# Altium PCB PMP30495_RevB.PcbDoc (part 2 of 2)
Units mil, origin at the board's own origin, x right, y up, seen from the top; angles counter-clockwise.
Board outline 6212.5 x 2387.5 mil, 2 copper layers (Top Layer, Bottom Layer), stack 62 mil thick; 95 components, 48 nets, 204 pads, 17 vias.
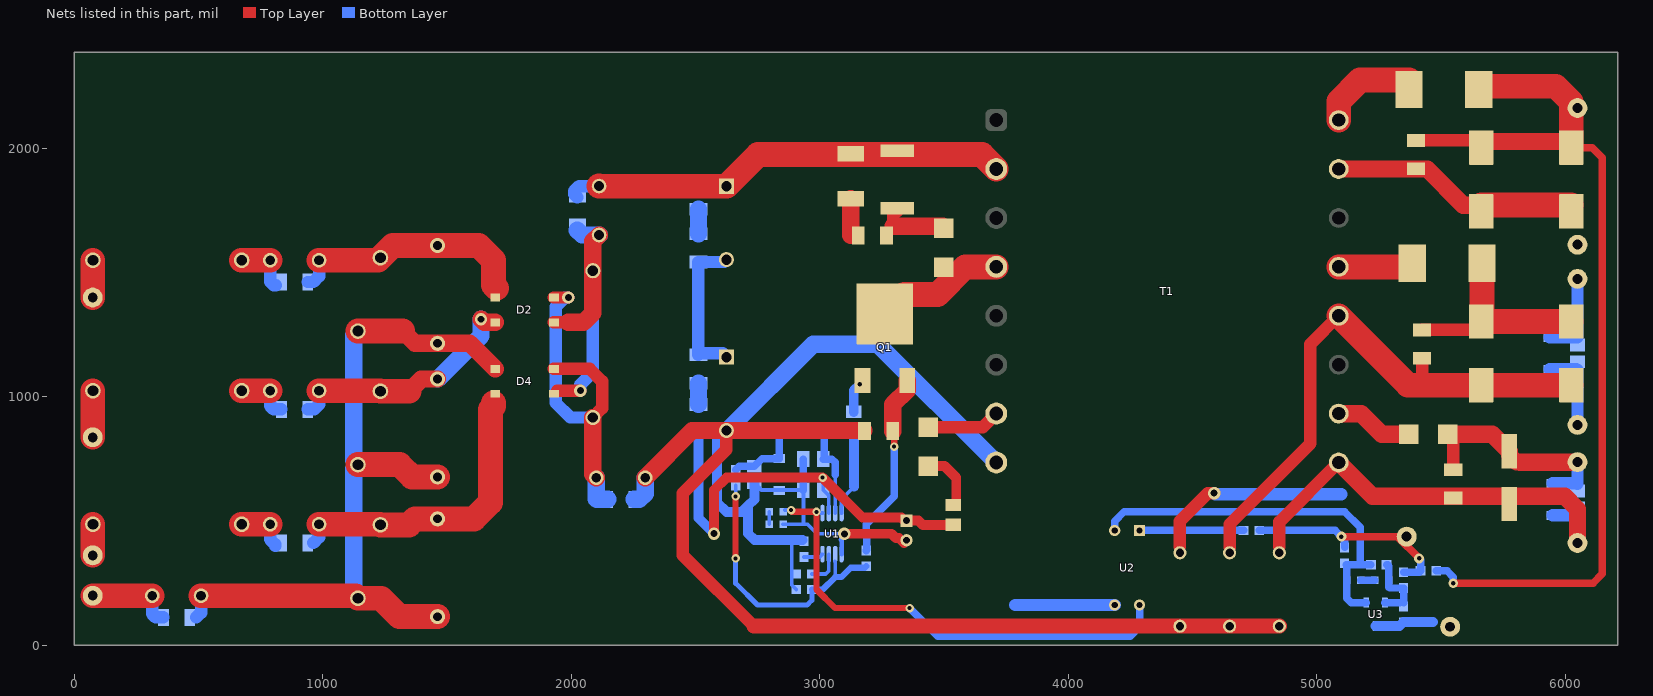
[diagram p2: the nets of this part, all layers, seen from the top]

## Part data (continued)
U3: "2.5V Low Iq Adjustable Precision Shunt Regulator, DBZ0003A (SOT-23-3)", Alternate Manufacturer="Texas Instruments"

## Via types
v1: diameter 34, hole 16, Top Layer to Bottom Layer, 7 vias
v2: diameter 50, hole 28, Top Layer to Bottom Layer, 6 vias
v3: diameter 40, hole 18, Top Layer to Bottom Layer, 4 vias

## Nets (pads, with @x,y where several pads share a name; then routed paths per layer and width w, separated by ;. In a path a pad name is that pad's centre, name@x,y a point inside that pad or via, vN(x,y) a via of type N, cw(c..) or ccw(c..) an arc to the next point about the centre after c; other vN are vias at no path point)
12Vout1: C3.1 C4.1 C5.1 D1.1 R16.2 TP2.1 | length 3730.7
  Top Layer w30: v3(5550,250) 6112.5,250 6150,287.5 6150,1962.5 6109.55,2002.95 C3.1@6025,2002.95
  Top Layer w50: C5.1@5400,2032.09 5633.37,2032.09 C4.1@5662.5,2002.95
  Top Layer w70: C4.1@5662.5,2027.95 C3.1@6025,2027.95
  Top Layer w100: D1.1@5652.99,2250 5962.5,2250 6025,2187.5 C3.1@6025,2027.95
  Bottom Layer w30: R16.2@5481.5,300 5525,300 5550,275 v3(5550,250)
GND1: C3.2 C4.2 C5.2 C16.1 R27.1 T1.15 TP3.1 TP12.1 U3.3 | length 2034.4
  Top Layer w50: C16.1@4450,397.64 4450,500 4562.5,612.5 v2(4587.5,612.5)
  Top Layer w70: T1.15@5088.98,1917.13 5445.37,1917.13 5590.45,1772.05 C4.2@5662.5,1772.05
  Top Layer w100: C4.2@5662.5,1772.05 C3.2@6025,1772.05
  Bottom Layer w40: U3.3@5237.5,77.76 5334.25,77.76 R27.1@5350,93.5 5468.5,93.5
  Bottom Layer w50: v2(4587.5,612.5) 4591.93,608.07 5100,608.07
GND2: C10.2 C11.2 C12.2 C18.1 D6.2 R10.1 T1.12 TP7.1 | length 2607.5
  Top Layer w50: C18.1@4650,394.29 4650,487.5 4975,812.5 4975,1212.6 T1.12@5088.98,1326.57 ; 5425,1047.05 C12.2@5425,1155.41
  Top Layer w100: T1.12@5088.98,1326.57 5368.5,1047.05 5425,1047.05 C10.2@5662.5,1047.05 C11.2@6025,1047.05
  Bottom Layer w50: D6.2@5937.5,1110.53 6044.59,1110.53 cw(c6044.59,1105.12) 6050,1105.12 TP7.1@6050,887.5
GND3: C14.2 C15.2 C19.1 D9.2 R14.1 T1.9 TP10.1 | length 1825.5
  Top Layer w50: C19.1@4850,397.64 4850,497.05 T1.9@5088.98,736.02
  Top Layer w70: T1.9@5088.98,736.02 5225,600 5998.13,600 6050,548.13 TP10.1@6050,412.5
  Bottom Layer w50: D9.2@5950,523.03 6048.03,523.03 ccw(c6048.03,525) 6050,525 TP10.1@6050,412.5
NetC1_1: C1.1 D2.3 L1.2 R1.2 RV1.2 | length 951.5
  Top Layer w100: L1.2@985.93,1550 1222.64,1550 RV1.2@1232.78,1560.14 1281.99,1609.35 C1.1@1462.5,1609.35 1628.15,1609.35 1687.5,1550 1687.5,1450 1700,1437.5
  Bottom Layer w50: R1.2@940.65,1462.5 962.5,1462.5 985.93,1485.93 985.93,1514.07
NetC1_2: C1.2 C7.2 C13.2 D4.3 L6.2 R15.2 RV1.1 RV2.1 RV3.1 | length 3127.3
  Top Layer w70: 1322.64,1264.86 1371.85,1215.65 C1.2@1462.5,1215.65 1591.24,1215.65 D4.3@1694.39,1112.5
  Top Layer w100: L6.2@510.93,200 RV3.1@1132.09,200 ; RV3.1@1142.22,189.86 1235.14,189.86 1309.35,115.65 C13.2@1462.5,115.65 ; RV2.1@1142.22,727.36 1310.14,727.36 1359.35,678.15 C7.2@1462.5,678.15 ; RV1.1@1142.22,1264.86 1322.64,1264.86
  Bottom Layer w50: 491.24,112.5 510.93,132.18 L6.2@510.93,200
  Bottom Layer w70: RV3.1@1142.22,189.86 1125,207.09 1125,710.14 RV2.1@1142.22,727.36 1125,744.59 1125,1247.64 RV1.1@1142.22,1264.86
NetC2_1: C2.1 L2.2 R2.2 R3.2 R4.2 R6.2 T1.2 | length 1936.1
  Top Layer w100: L2.2@2112.5,1848.43 2113.29,1847.64 C2.1@2625,1847.64 2752.36,1975 3653.15,1975 T1.2@3711.02,1917.13
  Bottom Layer w50: R2.2@2025,1803.15 2012.5,1815.65 2012.5,1828.74 2032.18,1848.43 L2.2@2112.5,1848.43 ; R3.2@2512.5,1869.59 2603.05,1869.59 C2.1@2625,1847.64
NetC2_2: C2.2 C9.1 R5.1 R9.2 | length 610.6
  Bottom Layer w50: C9.1@2625,1160.14 2610.14,1175 2517.91,1175 R9.2@2512.5,1169.59 R5.1@2512.5,1542.91 2615.55,1542.91 C2.2@2625,1552.36
NetC6_1: C6.1 D2.1 D4.1 L2.1 R2.1 | length 1190.4
  Top Layer w50: D2.1@1930.61,1300 1989.07,1300 ; D4.1@1943.11,1025 v2(2037.5,1025)
  Top Layer w70: 1989.07,1300 2050,1300 2087.5,1337.5 C6.1@2087.5,1507.78 2087.5,1626.57 L2.1@2112.5,1651.57
  Bottom Layer w50: v2(2037.5,1025) 2037.5,1050 2087.5,1100 C6.1@2087.5,1507.78
  Bottom Layer w70: 2025,1671.26 2044.68,1651.57 L2.1@2112.5,1651.57
NetC6_2: C6.2 D2.4 D4.4 L4.1 R8.1 | length 1441.9
  Top Layer w50: D4.4@1930.61,1112.5 2075,1112.5 2125,1062.5 2125,954.72 C6.2@2087.5,917.22 ; D2.4@1930.61,1400 v2(1989.07,1400)
  Top Layer w70: C6.2@2087.5,917.22 2087.5,689.07 L4.1@2101.57,675
  Bottom Layer w50: v2(1989.07,1400) 1975,1400 1937.5,1362.5 1937.5,976.57 1996.85,917.22 C6.2@2087.5,917.22
  Bottom Layer w70: L4.1@2101.57,675 2101.57,589.07 2103.15,587.5 R8.1@2146.85,587.5
NetC7_1: C7.1 D2.2 L3.2 R7.2 RV2.2 | length 981.9
  Top Layer w70: 1347.64,1022.64 1396.85,1071.85 C7.1@1462.5,1071.85 ; v2(1637.5,1312.5) 1650,1300 D2.2@1694.39,1300
  Top Layer w100: L3.2@985.93,1025 1230.41,1025 RV2.2@1232.78,1022.64 1347.64,1022.64
  Bottom Layer w50: R7.2@940.65,950 966.24,950 985.93,969.68 L3.2@985.93,1025
  Bottom Layer w70: C7.1@1462.5,1071.85 1637.5,1246.85 v2(1637.5,1312.5)
NetC8_1: C8.1 R4.1 | length 146.9
  Top Layer w70: 3125,1650 R4.1@3125,1796.95
NetC8_2: C8.2 D5.1 R6.1 | length 276.9
  Top Layer w50: 3296.26,1687.5 3296.26,1730.12 cw(c3312.5,1730.12) R6.1@3312.5,1746.36
  Top Layer w70: 3296.26,1687.5 3491.24,1687.5 cw(c3491.24,1678.74) D5.1@3500,1678.74
NetC10_1: C10.1 C11.1 C12.1 D3.1 D6.1 R10.2 TP5.1 | length 1196.3
  Top Layer w50: C12.1@5425,1269.59 5629.13,1269.59 C10.1@5662.5,1302.95
  Top Layer w100: D3.1@5665.49,1537.5 5665.49,1305.95 C10.1@5662.5,1302.95 C11.1@6025,1302.95
  Bottom Layer w50: D6.1@5937.5,1239.47 6046.87,1239.47 ccw(c6046.87,1242.6) 6050,1242.6 TP5.1@6050,1475
NetC13_1: C13.1 D4.2 L5.2 R12.2 RV3.2 | length 1213.8
  Top Layer w100: L5.2@985.93,487.5 RV3.2@1230.41,487.5 ; RV3.2@1232.78,485.14 1347.64,485.14 1371.85,509.35 C13.1@1462.5,509.35 1609.35,509.35 1675,575 1675,950 1687.5,962.5 1687.5,975
  Bottom Layer w50: 962.5,412.5 985.93,435.93 L5.2@985.93,487.5
NetC14_1: C14.1 C15.1 D7.1 D9.1 R14.2 TP8.1 | length 915.1
  Top Layer w50: D7.1@5528.74,850 5550,828.74 C15.1@5550,707.09
  Top Layer w70: D7.1@5528.74,850 5706.3,850 C14.1@5775,781.3 ccw(c5818.8,781.3) 5818.8,737.5 TP8.1@6050,737.5
  Bottom Layer w50: D9.1@5950,651.97 6048.03,651.97 cw(c6048.03,650) 6050,650 TP8.1@6050,737.5
NetC17_1: C17.1 C20.1 R11.1 R13.1 U1.2 | length 1820.8
  Top Layer w40: v2(2575,450) 2575,625 2625,675 v1(3012.5,675) 3173.29,514.21 3329.58,514.21 3341.92,501.87 C17.1@3350,501.87 3398.13,501.87 3415,485 R13.1@3537.5,485
  Bottom Layer w15: v1(3012.5,675) 3015,672.5 C20.1@3015,625 3037.2,602.8 U1.2@3037.2,532.68
  Bottom Layer w40: R11.1@2512.5,855.41 2512.5,512.5 v2(2575,450)
NetC21_1: C21.1 R19.1 R25.1 R27.2 U3.2 | length 274.7
  Bottom Layer w30: U3.2@5274.9,172.24 R27.2@5334.25,172.24 ; C21.1@5281.5,325 cw(c5281.5,316) 5290.5,316 R25.1@5290.5,262.5 5290.5,234.5 5294,231 R19.1@5350,231 R27.2@5350,172.24
NetC21_2: C21.2 C25.1 R18.1 U2.2 U3.1 | length 1533.1
  Bottom Layer w30: U2.2@4187.5,462.5 4187.5,500 4225,537.5 5112.5,537.5 5175,475 5175,325 ; R18.1@5118.5,325 5175,325 ; R18.1@5122,321.5 C25.1@5122,262.5 5122,190.5 5140.26,172.24 U3.1@5200.1,172.24 ; C21.2@5218.5,325 5175,325
NetC22_1: C22.1 U1.8 | length 78.8
  Bottom Layer w15: C22.1@2937.5,356 3000.3,356 U1.8@3011.61,367.32
NetC23_1: C23.1 R26.2 U1.3 | length 371.8
  Bottom Layer w15: U1.3@3062.8,532.68 3062.8,687.2
  Bottom Layer w30: R26.2@3019,862.5 3019,754 C23.1@3015,750 3050,750 3062.8,737.2 3062.8,687.2
NetC24_1: C24.1 R20.1 R28.2 U1.6 | length 1127.6
  Top Layer w25: v1(2661.82,599.5) 2661.82,350.68 v1(2662.5,350)
  Bottom Layer w15: v1(2661.82,599.5) 2661.82,590.68 2662.5,590 R28.2@2662.5,643.5 ; U1.6@3061.44,337.7 3062.5,336.64 3062.5,275
  Bottom Layer w20: v1(2662.5,350) 2662.5,250 2750,162.5 2950,162.5 2969,181.5 C24.1@2969,225
  Bottom Layer w25: C24.1@2969,225 3012.5,225 3062.5,275 3087.5,275 3125,312.5 3181.5,312.5 R20.1@3187.5,318.5
NetC25_2: C25.2 R25.2 | length 56.5
  Bottom Layer w30: C25.2@5178,262.5 R25.2@5234.5,262.5
NetC26_1: C26.1 R22.1 | length 50
  Bottom Layer w15: C26.1@2797,487.5 R22.1@2797,537.5
NetC27_1: C27.1 D10.1 R26.1 R28.1 | length 408.2
  Bottom Layer w30: R28.1@2662.5,706.5 2676.97,720.96 C27.1@2737.5,720.96 2768.5,751.97 D10.1@2837.5,751.97 2837.5,837.5 2862.5,862.5 R26.1@2956,862.5
NetD1_2: D1.2 T1.16 | length 393.7
  Top Layer w100: T1.16@5088.98,2113.98 5088.98,2188.98 5175,2275 D1.2@5372.01,2275
NetD3_2: D3.2 T1.13 | length 281.5
  Top Layer w100: T1.13@5088.98,1523.43 D3.2@5370.43,1523.43
NetD5_2: D5.2 Q1.4 T1.4 | length 415.8
  Top Layer w100: Q1.4@3341.14,1412.5 3475,1412.5 3585.93,1523.43 T1.4@3711.02,1523.43
NetD7_2: D7.2 T1.10 | length 316.6
  Top Layer w70: T1.10@5088.98,932.87 5179.63,932.87 5262.5,850 D7.2@5371.26,850
NetD8_1: D8.1 R13.2 | length 246.8
  Top Layer w40: D8.1@3437.5,721.26 3503.74,721.26 3550,675 3550,577.5 R13.2@3537.5,565
NetD8_2: D8.2 T1.7 | length 295.9
  Top Layer w50: D8.2@3437.5,878.74 3656.89,878.74 T1.7@3711.02,932.87
NetL1_1: L1.1 R1.1 RF1.1 | length 230
  Top Layer w100: RF1.1@674.21,1550 L1.1@789.07,1550
  Bottom Layer w50: L1.1@789.07,1550 789.07,1464.07 803.15,1450 812.5,1450
NetL3_1: L3.1 R7.1 RF2.1 | length 226.9
  Top Layer w100: RF2.1@674.21,1025 L3.1@789.07,1025
  Bottom Layer w50: L3.1@789.07,1025 789.07,964.07 803.15,950 R7.1@834.35,950
NetL5_1: L5.1 R12.1 RF3.1 | length 210.5
  Top Layer w100: RF3.1@674.21,487.5 L5.1@789.07,487.5
  Bottom Layer w50: L5.1@789.07,487.5 789.07,426.57 808.76,406.89 808.76,400
NetL6_1: L6.1 R15.1 TP9.1 | length 363.6
  Top Layer w100: TP9.1@75,200 L6.1@314.07,200
  Bottom Layer w50: L6.1@314.07,200 314.07,126.57 328.15,112.5 R15.1@359.35,112.5
NetQ1_1: Q1.1 R17.2 | length 143.2
  Top Layer w40: v3(3162.5,1050) Q1.1@3178.64,1066.14
  Bottom Layer w40: R17.2@3137.5,940 3137.5,1025 v3(3162.5,1050)
NetQ1_3: Q1.3 R20.2 R24.2 | length 759.4
  Top Layer w25: R24.2@3294.59,862.5 3300,857.09 v1(3300,800)
  Top Layer w70: R24.2@3294.59,862.5 3294.59,969.59 3352.26,1027.26 Q1.3@3352.26,1066.14
  Bottom Layer w30: R20.2@3187.5,381.5 3187.5,383.08 3190,385.58 3190,439.42 3187.5,441.92 3187.5,487.5 3300,600 v1(3300,800)
NetR3_1: R3.1 R5.2 | length 98.3
  Bottom Layer w70: R5.2@2512.5,1657.09 R3.1@2512.5,1755.41
NetR9_1: R9.1 R11.2 | length 85.8
  Bottom Layer w70: R11.2@2512.5,969.59 R9.1@2512.5,1055.41
NetR16_1: R16.1 R18.2 R19.2 R21.2 TP11.1 | length 853.8
  Top Layer w30: v3(5100,437.5) 5325,437.5 v3(5412.5,350)
  Bottom Layer w30: R21.2@4769,462.5 5075,462.5 v3(5100,437.5) 5112.5,425 R18.2@5112.5,394 ; R19.2@5350,294 R16.1@5412.5,294 ; v3(5412.5,350) 5418.5,344 R16.1@5418.5,300
NetR17_1: R17.1 U1.4 | length 348.4
  Bottom Layer w15: U1.4@3088.39,532.68 3088.39,588.39 3138.39,638.39
  Bottom Layer w40: R17.1@3137.5,860 3138.39,859.11 3138.39,638.39
NetR21_1: R21.1 U2.1 | length 418.5
  Bottom Layer w30: U2.1@4287.5,462.5 R21.1@4706,462.5
NetR22_2: R22.2 U1.1 U2.4 | length 1971.5
  Top Layer w25: v1(2885.5,544.5) ccw(c2892.5,544.5) 2892.5,537.5 v1(2987.5,537.5) 2987.5,225 3062.5,150 v1(3362.5,150)
  Bottom Layer w15: R22.2@2860,544.5 v1(2885.5,544.5) ; v1(2987.5,537.5) 2977.17,537.5 2981.99,532.68 U1.1@3011.61,532.68
  Bottom Layer w30: v1(3362.5,150) 3475,37.5 4250,37.5 4287.5,75 U2.4@4287.5,162.5
NetR23_2: R23.2 U1.7 | length 140.9
  Bottom Layer w15: R23.2@2969,287.5 3025,287.5 3037.2,299.7 U1.7@3037.2,367.32
NetRF1_2: RF1.2 TP1.1 | length 149.2
  Top Layer w100: TP1.1@75,1400 RF1.2@75,1549.21
NetRF2_2: RF2.2 TP4.1 | length 186.7
  Top Layer w100: TP4.1@75,837.5 RF2.2@75,1024.21
NetRF3_2: RF3.2 TP6.1 | length 124.2
  Top Layer w100: TP6.1@75,362.5 RF3.2@75,486.71
PGND: C9.2 C16.2 C17.2 C18.2 C19.2 C20.2 C22.2 C23.2 C24.2 C26.2 C27.2 D10.2 L4.2 R8.2 R23.1 R24.1 T1.8 U1.5 U2.3 | length 8194.3
  Top Layer w40: v2(3100,449.21) 3289.81,449.21 3306.75,432.26 3319.61,432.26 C17.2@3339.37,412.5
  Top Layer w50: C9.2@2625,864.86 2625,787.5 2450,612.5 2450,362.5 2735.14,77.36
  Top Layer w60: 2735.14,77.36 4537.5,77.36 C19.2@4850,77.36
  Top Layer w70: L4.2@2298.43,675 2488.29,864.86 C9.2@2625,864.86 R24.1@3178.05,864.86
  Bottom Layer w15: C27.2@2737.5,654.04 2766.54,625 C20.2@2935,625 2935,487.5 ; C26.2@2853,487.5 2935,487.5 ; C24.2@2906,225 2887.5,243.5 2887.5,412.5 2894,419 C22.2@2937.5,419 ; v2(3100,449.21) 2989.76,449.21 2951.48,487.5 2935,487.5
  Bottom Layer w18: 3084.43,425 3088.39,421.04 U1.5@3088.39,367.32
  Bottom Layer w30: C20.2@2935,625 C23.2@2935,750
  Bottom Layer w40: C9.2@2625,864.86 2587.5,827.36 2587.5,575 2625,537.5 2687.5,537.5 2712.5,562.5 ; C27.2@2737.5,654.04 2737.5,587.5 2712.5,562.5 ; C22.2@2931.5,425 2737.5,425 2712.5,450 2712.5,562.5
  Bottom Layer w50: 3787.5,162.5 U2.3@4187.5,162.5
  Bottom Layer w70: R8.2@2253.15,587.5 2275,587.5 2298.43,610.93 L4.2@2298.43,675 ; C9.2@2625,864.86 2627.36,864.86 2975,1212.5 3234.55,1212.5 T1.8@3711.02,736.02
pads on no net: T1.1 T1.3 T1.5 T1.6 T1.11 T1.14

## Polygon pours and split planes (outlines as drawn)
NetD5_2 on Top Layer "Top Layer-No Net" (solid, pour order 4): 3362.5,1487.5 ccw(c3362.5,1537.5) 3412.5,1537.5 cw(c3450,1537.5) 3450,1575 3712.5,1575 cw(c3712.5,1525) 3762.5,1525 3762.5,1512.5 cw(c3725,1512.5) 3725,1475 3612.5,1475 ccw(c3612.5,1462.5) 3600,1462.5 3600,1450 cw(c3512.5,1450) 3512.5,1362.5 3412.5,1362.5 ccw(c3412.5,1337.5) 3387.5,1337.5 3387.5,1225 cw(c3362.5,1225) 3362.5,1200 3150,1200 cw(c3150,1237.5) 3112.5,1237.5 3112.5,1437.5 cw(c3162.5,1437.5) 3162.5,1487.5
NetC8_2 on Top Layer "Top Layer-No Net 1" (solid, pour order 6): 3260.73,1800 ccw(c3260.73,1775) 3235.73,1775 3235.73,1630.51 ccw(c3262.5,1630.51) 3262.5,1603.74 3366.24,1603.74 ccw(c3366.24,1625) 3387.5,1625 cw(c3400,1625) 3400,1637.5 3543.9,1637.5 ccw(c3543.9,1662.5) 3568.9,1662.5 3568.9,1768.6 ccw(c3537.5,1768.6) 3537.5,1800
NetC8_1 on Top Layer "Top Layer-No Net 2" (solid, pour order 8): 3137.5,1602.36 3164.86,1602.36 ccw(c3164.86,1625) 3187.5,1625 3187.5,1837.5 ccw(c3175,1837.5) 3175,1850 3085.04,1850 ccw(c3085.04,1825) 3060.04,1825 3060.04,1627.46 ccw(c3087.5,1627.46) 3087.5,1600
PGND on Top Layer "Top Layer-No Net 3" (solid, pour order 12): 3800,25 ccw(c3800,37.5) 3812.5,37.5 3812.5,875 ccw(c3787.5,875) 3787.5,900 2262.5,900 ccw(c2262.5,875) 2237.5,875 2237.5,62.5 ccw(c2275,62.5) 2275,25
NetD1_2 on Top Layer "Top Layer-No Net 5" (solid, pour order 18): 5125,2062.5 ccw(c5125,2087.5) 5150,2087.5 5150,2137.5 cw(c5175,2137.5) 5175,2162.5 5450,2162.5 ccw(c5450,2175) 5462.5,2175 5462.5,2342.42 ccw(c5437.5,2342.42) 5437.5,2367.42 5042.42,2367.42 ccw(c5042.42,2350) 5025,2350 5025,2087.5 ccw(c5050,2087.5) 5050,2062.5
12Vout1 on Top Layer "Top Layer-No Net 6" (solid, pour order 20): 5587.5,2367.42 cw(c5596.21,2358.71) 5604.92,2367.42 6157.58,2367.42 cw(c6157.58,2337.5) 6187.5,2337.5 6187.5,1925 cw(c6162.5,1925) 6162.5,1900 5600,1900 cw(c5600,1950) 5550,1950 5550,2329.92 cw(c5587.5,2329.92) 5587.5,2367.42 5612.5,2367.42
GND1 on Top Layer "Top Layer-No Net 7" (solid, pour order 22): 5025,1962.5 cw(c5037.5,1962.5) 5037.5,1975 5450,1975 cw(c5450,1962.5) 5462.5,1962.5 5575,1850 6162.5,1850 cw(c6162.5,1825) 6187.5,1825 6187.5,1712.5 cw(c6162.5,1712.5) 6162.5,1687.5 5062.5,1687.5 cw(c5062.5,1725) 5025,1725
GND1 on Top Layer "Top Layer-No Net 4" (solid, pour order 24): 6150,12.5 ccw(c6150,50) 6187.5,50 6187.5,400 ccw(c6137.5,400) 6137.5,450 5175,450 ccw(c5175,425) 5150,425 5150,237.5 ccw(c5175,237.5) 5175,212.5 5357.32,30.18 ccw(c5400,72.86) 5400,12.5
NetD3_2 on Top Layer "Top Layer-No Net 8" (solid, pour order 26): 5025,1575 cw(c5062.5,1575) 5062.5,1612.5 5500,1612.5 cw(c5500,1600) 5512.5,1600 5512.5,1462.5 cw(c5487.5,1462.5) 5487.5,1437.5 5050,1437.5 cw(c5050,1462.5) 5025,1462.5
NetC10_1 on Top Layer "Top Layer-No Net 9" (solid, pour order 28): 5562.5,1587.5 cw(c5587.5,1587.5) 5587.5,1612.5 6175,1612.5 cw(c6175,1600) 6187.5,1600 6187.5,1212.5 cw(c6175,1212.5) 6175,1200 5550,1200 cw(c5550,1225) 5525,1225 5512.5,1237.5 5325,1237.5 5225,1337.5 5225,1412.5 ccw(c5200,1412.5) 5200,1437.5
GND2 on Top Layer "Top Layer-No Net 10" (solid, pour order 30): 5250,1187.5 5470.18,1187.5 cw(c5470.18,1162.5) 5495.18,1162.5 ccw(c5507.68,1162.5) 5507.68,1150 6125,1150 cw(c6125,1125) 6150,1125 6150,912.5 cw(c6125,912.5) 6125,887.5 5887.5,887.5 cw(c5887.5,925) 5850,925 ccw(c5825,925) 5825,950 5275,950 5187.5,1037.5 4992.68,1037.5 cw(c4992.68,1080.18) 4962.5,1050 4958.84,1053.66 cw(c4980.18,1075) 4950,1075 4950,1350 cw(c4975,1350) 4975,1375 5112.5,1375
NetC14_1 on Top Layer "Top Layer-No Net 11" (solid, pour order 32): 5500,675 cw(c5500,700) 5475,700 5475,875 cw(c5487.5,875) 5487.5,887.5 5800,887.5 cw(c5800,875) 5812.5,875 5812.5,687.5 cw(c5800,687.5) 5800,675
PGND on Bottom Layer "Bottom Layer-No Net" (solid, pour order 10): 3787.5,1250 cw(c3787.5,1228.05) 3809.45,1228.05 3809.45,34.45 cw(c3787.5,34.45) 3787.5,12.5 2212.5,12.5 cw(c2212.5,75) 2150,75 2150,1187.5 cw(c2212.5,1187.5) 2212.5,1250
GND1 on Bottom Layer "Bottom Layer-No Net 1" (solid, remove dead copper, pour order 14): 5050,2287.5 cw(c5125,2287.5) 5125,2362.5 6125,2362.5 cw(c6125,2300) 6187.5,2300 6187.5,50 cw(c6150,50) 6150,12.5 5367.67,12.5 cw(c5367.67,319.11) 5061.06,319.11

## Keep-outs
Keep-Out Layer:
  text ".Layer_Name" at 577,-858.49 h60

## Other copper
Top Layer:
  text ".Layer_Name" at 577,-858.49 h60
Bottom Layer:
  text ".Layer_Name" at 577,-858.49 h60

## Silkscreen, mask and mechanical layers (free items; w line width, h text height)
Top Overlay:
  text "PMP30495_RevB" at 425,2012.5 h80
  text ".Layer_Name" at 577,-858.49 h50
Bottom Overlay:
  text ".Layer_Name" at 577,-858.49 h40
Top Paste:
  text ".Layer_Name" at 577,-858.49 h60
Bottom Paste:
  text ".Layer_Name" at 577,-858.49 h60
Top Solder:
  text ".Layer_Name" at 577,-858.49 h60
  text ".Layer_Name" at 577,-858.49 h60
Bottom Solder:
  text ".Layer_Name" at 577,-858.49 h60
Drill Guide:
  text ".Layer_Name" at 577,-858.49 h60
M1 Board Outline:
  the board outline again, w10
  text ".Layer_Name" at 577,-858.49 h60
M2 Board Dimensions:
  rectangle: 0,-275 125,-150
  rectangle: 125,-400 500,-275
  lines w7: 0,-275 1000,-275 ; 125,-400 125,-150 ; 250,-400 250,-150 ; 500,-400 500,-150 ; 750,-400 750,-150 ; 0,-400 1000,-400 1000,-150 0,-150 0,-400
  text ".Layer_Name" at 577,-858.49 h60
M3 3D STEP Top:
  text ".Layer_Name" at 577,-858.49 h60
M4 3D STEP Bottom:
  text ".Layer_Name" at 577,-858.49 h60
M5 Assembly Top:
  lines w10: -292,-930.17 6308,-930.17 ; -292,-726.83 6310,-726.83 ; -292,-523.5 -292,-1133.5 3713,-1133.5 6310,-1133.5 6310,-523.5 -291.5,-523.5 -291.5,-1133.5 1284,-1133.5 ; 2173,-1133.5 2173,-523.5 ; 3440,-726.83 3440,-523.5 ; 4280,-726.83 4280,-523.5 ; 4902,-1140 4902,-937.17
  text "COMPONENTS MARKED 'DNP' SHOULD NOT BE POPULATED." at 1153.5,-318.5 h60
  text "ASSEMBLY VARIANT:" at 1153,-434 h60
  text ".VariantName" at 2189,-434 h60
  text "PCB VIEWED FROM TOP SIDE" at -228.5,-655.67 h60
  text "BOARD #:" at 2248,-655.67 h60
  text ".PRJ_Number" at 2793.5,-655.67 h60
  text "REV:" at 3638,-655.67 h60
  text ".PCB_Rev" at 3929.5,-655.67 h60
  text "SVN REV:" at 4476,-655.67 h60
  text ".VersionControl_RevNumber" at 4982,-655.67 h60
  text "TID #:" at 2248,-859 h60
  text ".TID" at 2793.5,-859 h60
  text "PLOT NAME =" at -228.5,-1064.34 h60
  text ".plot_File_Name" at 577,-1064.34 h60
  text "GENERATED    :" at 2250,-1064.34 h60
  text ".Print_Date" at 3119.5,-1064.34 h60
  text ".Print_Time" at 3848.5,-1064.34 h60
  text "TEXAS INSTRUMENTS" at 5113,-1064.34 h60
M6 Assembly Bottom:
  lines w10: -292.5,-727.33 6309.5,-727.33 ; -290.5,-930.67 6309.5,-930.67 ; 1115.5,-1140.5 1115.5,-937.67 ; 1737.5,-727.33 1737.5,-524 ; 2577.5,-727.33 2577.5,-524 ; 3844.5,-1134 3844.5,-524 ; 4733.5,-1134 6309,-1134 6309,-524 -292.5,-524 -292.5,-1134 2304.5,-1134 6309.5,-1134 6309.5,-524
  text "COMPONENTS MARKED 'DNP' SHOULD NOT BE POPULATED." at 6102,-318 h60
  text ".VariantName" at 5058,-434 h60
  text "ASSEMBLY VARIANT:" at 6097,-434 h60
  text ".VersionControl_RevNumber" at 1035.5,-656.17 h60
  text "SVN REV:" at 1541.5,-656.17 h60
  text ".PCB_Rev" at 2088,-656.17 h60
  text "REV:" at 2379.5,-656.17 h60
  text ".PRJ_Number" at 3224,-656.17 h60
  text "BOARD #:" at 3769.5,-656.17 h60
  text "PCB VIEWED FROM BOTTOM SIDE" at 6246,-656.17 h60
  text ".TID" at 3224,-859.5 h60
  text "TID #:" at 3769.5,-859.5 h60
  text "TEXAS INSTRUMENTS" at 904.5,-1064.84 h60
  text ".Print_Time" at 2169,-1064.84 h60
  text ".Print_Date" at 2898,-1064.84 h60
  text "GENERATED    :" at 3767.5,-1064.84 h60
  text ".plot_File_Name" at 5440.5,-1064.84 h60
  text "PLOT NAME =" at 6246,-1064.84 h60
M9 Title Sheet:
  drawing of 57 lines, arcs and shapes, not listed
  text "1" at 739.84,8036.5 h70
  text "2" at 3235.5,8036.5 h70
  text "3" at 5724.84,8036.5 h70
  text "4" at 8231.51,8036.5 h70
  text "5" at 10730.5,8036.5 h70
  text "6" at 13235.5,8036.5 h70
  text "A" at -416.5,6893.5 h70
  text "A" at 14383.5,6893.5 h70
  text "B" at -416.5,4513.5 h70
  text "B" at 14383.5,4513.5 h70
  text "C" at -416.5,2138.5 h70
  text "C" at 14383.5,2138.5 h70
  text "PROJECT TITLE:" at 11343.5,277.5 h45
  text ".PRJ_Title" at 11393.5,144.17 h70
  text "DESIGNED FOR:" at 11343.5,-23.5 h45
  text ".PRJ_Customer" at 11393.5,-163.5 h70
  text "D" at -416.5,-231.5 h70
  text "D" at 14383.5,-231.5 h70
  text "FILE NAME:" at 11343.5,-323.5 h45
  text ".PCB_File_Name_No_Path" at 11393.5,-443.5 h70
  text "Texas Instruments (TI) and/or its licensors do not warrant the accuracy or completeness of this specification" at 6374,-605.34 h45
  text "ENGINEER:" at 11343.5,-613.5 h45
  text "LAYOUT BY:" at 12848.5,-613.5 h45
  text "or any information contained therein. TI and/or its licensors do not warrant that this design will meet" at 6329.01,-718 h45
  text ".PRJ_Engineer" at 11393.5,-768.49 h70
  text ".PCB_Layout" at 12899,-768.49 h70
  text "the specifications, will be suitable for your application or fit for any particular purpose, or will operate in" at 6329.01,-830.67 h45
  text ".Layer_Name" at 577,-858.49 h60
  text "ALTIUM DESIGNER VERSION:" at 12848.5,-923.5 h45
  text "an implementation. TI and/or its licensors do not warrant that the design is production worthy. You should" at 6329.01,-943.33 h45
  text "completely validate and test your design implementation to confirm the system functionality for your application." at 6374,-1056 h45
  text ".print_Scale" at 11393.5,-1056.83 h70
  text ".Application_BuildNumber" at 12899,-1056.83 h70
  text "1" at 739.84,-1263.5 h70
  text "2" at 3235.5,-1263.5 h70
  text "3" at 5724.84,-1263.5 h70
  text "4" at 8231.51,-1263.5 h70
  text "5" at 10730.5,-1263.5 h70
  text "6" at 13235.5,-1263.5 h70
M10 Fab Notes:
  text ".Layer_Name" at 577,-858.49 h60
M11 Gerber Information:
  lines w10: -292,-930.17 6308,-930.17 ; -292,-726.83 6310,-726.83 ; -292,-523.5 -292,-1133.5 3713,-1133.5 6310,-1133.5 6310,-523.5 -291.5,-523.5 -291.5,-1133.5 1284,-1133.5 ; 2173,-1133.5 2173,-523.5 ; 3440,-726.83 3440,-523.5 ; 4280,-726.83 4280,-523.5 ; 4902,-1140 4902,-937.17
  text "ALL ARTWORK VIEWED FROM TOP SIDE" at -228.5,-655.67 h60
  text "BOARD #:" at 2248,-655.67 h60
  text ".PRJ_Number" at 2793.5,-655.67 h60
  text "REV:" at 3638,-655.67 h60
  text ".PCB_Rev" at 3929.5,-655.67 h60
  text "SVN REV:" at 4476,-655.67 h60
  text ".VersionControl_RevNumber" at 4982,-655.67 h60
  text "LAYER NAME =" at -228.5,-858.49 h60
  text "TID #:" at 2248,-859 h60
  text ".TID" at 2793.5,-859 h60
  text "PLOT NAME =" at -228.5,-1064.34 h60
  text ".plot_File_Name" at 577,-1064.34 h60
  text "GENERATED    :" at 2250,-1064.34 h60
  text ".Print_Date" at 3119.5,-1064.34 h60
  text ".Print_Time" at 3848.5,-1064.34 h60
  text "TEXAS INSTRUMENTS" at 5113,-1064.34 h60
M12 Stackup:
  text ".Layer_Name" at 577,-858.49 h60
M13 Component Bodies Top:
  text ".Layer_Name" at 577,-858.49 h60
M14 Component Bodies Bottom:
  text ".Layer_Name" at 577,-858.49 h60
M15 Courtyards Top:
  text ".Layer_Name" at 577,-858.49 h60
M16 Courtyards Bottom:
  text ".Layer_Name" at 577,-858.49 h60
Drill Drawing:
  text ".Layer_Name" at 577,-858.49 h60
M17 Embedded Cavity:
  text ".Layer_Name" at 577,-858.49 h60
M18 Embedded Assembly:
  text ".Layer_Name" at 577,-858.49 h60
M19 Embedded Keepout:
  text ".Layer_Name" at 577,-858.49 h60

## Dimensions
0,-400 to 1000,-400 on M2 Board Dimensions
0,0 to 0,2387.5 on M2 Board Dimensions
0,0 to 6212.5,0 on M2 Board Dimensions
